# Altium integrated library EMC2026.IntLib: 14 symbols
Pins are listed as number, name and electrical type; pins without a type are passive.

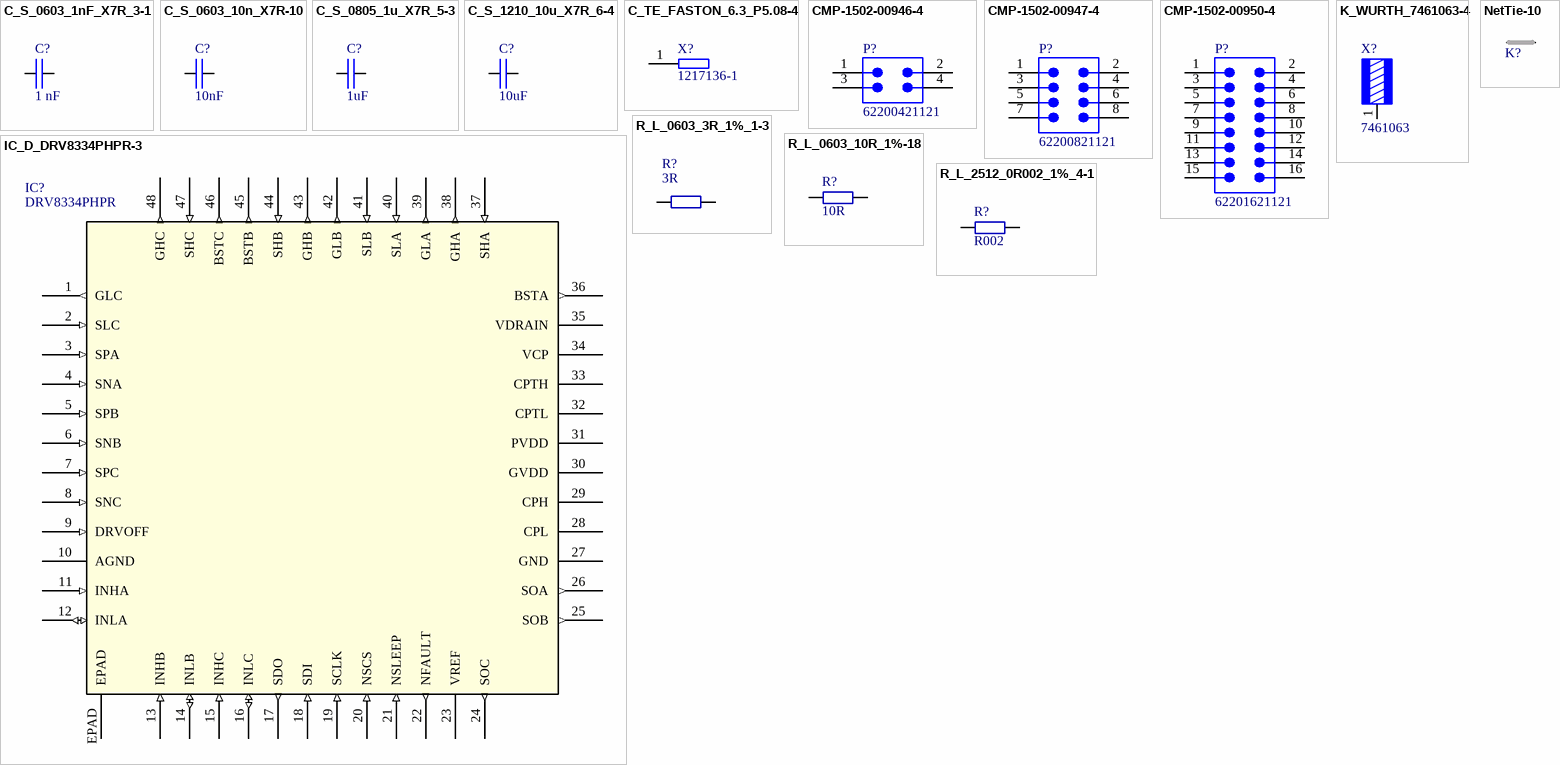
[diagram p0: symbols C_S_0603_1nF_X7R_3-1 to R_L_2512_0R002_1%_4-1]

## C_S_0603_1nF_X7R_3-1
designator C?, comment HRVal: 1 nF  (hidden comment: C_S_0603_1nF_X7R_3)
Single capacitor 1nF 5% AEC; Manufacturer code: VJ0603Y102JXAAC; Manufacturer: VISHAY; Tolerance: 5; SAP Name: KONDENZATOR VJ0603Y102JXAAC VIS; Value [F]: 1e-9; Voltage: 50; BS: BS1556; Class: 15562
footprint FPR_0603_C_R0 (SMD Reflow)
pins: 1, 2

## C_S_0603_10n_X7R-10
designator C?, comment HRVal: 10nF  (hidden comment: C_S_0603_10n_X7R)
Single capacitor 10 nF; Manufacturer code: 06035C103K4Z4A; Manufacturer: AVX; SAP Name: KONDENZATOR 06035C103K4Z4A AVX; Voltage: 50; BS: BS1556; Class: 15562; Tolerance: 10; Value [F]: 10e-9; SAP Ident: 628870
footprint FPR_0603_C_R0 (SMD Reflow)
pins: 1, 2

## C_S_0805_1u_X7R_5-3
designator C?, comment HRVal: 1uF  (hidden comment: C_S_0805_1u_X7R_5)
Single capacitor 1uF 10% soft-term AEC200; Manufacturer: Murata; Manufacturer code: GCJ21BR71H105KA01L; SAP Name: KONDENZATOR GCJ21BR71H105KA01L MUR; BS: BS1556; Tolerance: 10; Value [F]: 1e-6; Voltage: 50; SAP Ident: 927197; Class: 15562
footprint FPR_0805_C_R0_1 (SMD Reflow)
pins: 1, 2

## C_S_1210_10u_X7R_6-4
designator C?, comment HRVal: 10uF  (hidden comment: C_S_1210_10u_X7R_6)
Single capacitor 10uF; Manufacturer: AVX; Manufacturer code: 12105C106K4Z4A; BS: BS1556; SAP Name: KONDENZATOR 12105C106K4Z4A AVX; Tolerance: 10; Value [F]: 10e-6; Voltage: 50; SAP Ident: 919177; Class: 15562; Shelf life: 12 months
footprint FPR_1210_C_R0_10u (SMD Reflow)
pins: 1, 2

## C_TE_FASTON_6.3_P5.08-4
designator X?, comment Manufacturer code: 1217136-1  (hidden comment: C_TE_FASTON_6.3_P5.08)
FASTON 6.3 P5.08 Pokončni; Manufacturer: TE CONNECTIVITY; Voltage: /; SAP Ident: 1163972; SAP Name: KONEKTOR 1217136-1 TEC; BS: BS1552; AEC: No; Class: 15526
footprint FPR_TAB_6.3_P5.08_Pokončni (FASTON 6.3 P5.08 Pokončni)
pins: 1

## CMP-1502-00946-4
designator P?, comment 62200421121
THT Vertical Pin Header WR-PHD, Pitch 1.27 mm, Dual Row, 4 pins; Row Spacing: 1.27mm; Gender: Male; Number of Positions: 4; Contact Resistance: 20mΩ; Current Rating: 1A; System: Connector; Connector Type: Male Pin
footprint 62200421121 (THT Vertical Pin Header WR-PHD, Pitch 1.27 mm, Dual Row, 4 pins)
pins: 1, 2, 3, 4

## CMP-1502-00947-4
designator P?, comment 62200821121
THT Vertical Pin Header WR-PHD, Pitch 1.27 mm, Dual Row, 8 pins; System: Connector; Row Spacing: 1.27mm; Connector Type: Male Pin; Contact Resistance: 20mΩ; Number of Contacts: 8; Current Rating: 1A; Gender: Male
footprint 62200821121 (THT Vertical Pin Header WR-PHD, Pitch 1.27 mm, Dual Row, 8 pins)
pins: 1, 2, 3, 4, 5, 6, 7, 8

## CMP-1502-00950-4
designator P?, comment 62201621121
THT Vertical Pin Header WR-PHD, Pitch 1.27 mm, Dual Row, 16 pins; Number of Positions: 16; Pitch: 1.27mm; Connector Type: Male Pin; Gender: Male; Current Rating: 1A; Contact Resistance: 20mΩ; System: Connector
footprint 62201621121 (THT Vertical Pin Header WR-PHD, Pitch 1.27 mm, Dual Row, 16 pins)
pins: 1, 2, 3, 4, 5, 6, 7, 8, 9, 10, 11, 12, 13, 14, 15, 16

## IC_D_DRV8334PHPR-3
designator IC?, comment Manufacturer code: DRV8334PHPR  (hidden comment: IC_D_DRV8334PHPR)
Three phase MOSFET driver; Manufacturer: TI; AEC: No; BS: BS1557; Class: 15571; Output Current: 1000 / 2000 mA; Output Voltage: 60; SAP Ident: 1125019; SAP Name: GONILNIK DRV8334PHPR TI
footprint FPR_HTQFP_48P (SMD HTQFP 48P)
pins: 1 GLC (out), 2 SLC (in), 3 SPA (in), 4 SNA (in), 5 SPB (in), 6 SNB (in), 7 SPC (in), 8 SNC (in), 9 DRVOFF (in), 10 AGND (power), 11 INHA (in), 12 INLA (io), 13 INHB (in), 14 INLB (io), 15 INHC (in), 16 INLC (io), 17 SDO (out), 18 SDI (in), 19 SCLK (in), 20 NSCS (in), 21 NSLEEP (in), 22 NFAULT (out), 23 VREF (power), 24 SOC (out), 25 SOB (out), 26 SOA (out), 27 GND (power), 28 CPL (power), 29 CPH (power), 30 GVDD (power), 31 PVDD (power), 32 CPTL (power), 33 CPTH (power), 34 VCP (power), 35 VDRAIN (power), 36 BSTA (out), 37 SHA (in), 38 GHA (out), 39 GLA (out), 40 SLA (in), 41 SLB (in), 42 GLB (out), 43 GHB (out), 44 SHB (in), 45 BSTB (out), 46 BSTC (out), 47 SHC (in), 48 GHC (out), EPAD

## K_WURTH_7461063-4
designator X?, comment Manufacturer code: 7461063  (hidden comment: K_WURTH_7461063)
Connector POWER Wurth 7461063; Manufacturer: WURTH ELEKTRONIK; UL: /; MaxCurrent: 160; AEC: No; Class: 15526; ReleaseDateNum: 45705.4409943981; Voltage: 300; BS: BS1552; SAP Name: KONEKTOR 7461063 WUE; SAP Ident: 1144983
footprint FPR_K_1P_WURTH (WURTH 1P terminal connector)
pins: 1

## NetTie-10
designator K?, comment NetTie  (value not drawn)  (net tie, no BOM)
Net tie
footprint FPR_NETTIE_0_3 (Net tie, 0.3 mm)
pins: 1, 2

## R_L_0603_3R_1%_1-3
designator R?, comment HRVal: 3R  (hidden comment: R_L_0603_3R_1%_1)
Upor 3R 0603 1% 100mW; Manufacturer code: CRCW06033R00FKEA; Manufacturer: VISHAY; SAP Name: UPOR CRCW06033R00FKEA VIS; Tolerance: 1; Power: 100e-3; ReleaseDateNum: 45455.4806185648; BS: BS1556; Class: 15561; Value [Ohm]: 3; SAP Ident: 1125027
footprint FPR_0603_R_R0_1 (SMD Reflow)
pins: 1, 2

## R_L_0603_10R_1%-18
designator R?, comment HRVal: 10R  (hidden comment: R_L_0603_10R_1%)
Upor 10R 0603 1% 100mW; Manufacturer: ASJ; Manufacturer code: CR16-10R0-FY; Class: 15561; BS: BS1556; Shelf life: 12 months; SAP Name: UPOR CR16-10R0-FY ASJ; SAP Ident: 220173; Tolerance: 1; Power: 100e-3; Value [Ohm]: 10
footprint FPR_0603_R_R0 (SMD Reflow)
simulation model GenericR
footprint FPR_0603_R_R0_1 (SMD Reflow)
pins: 1, 2

## R_L_2512_0R002_1%_4-1
designator R?, comment HRVal: R002  (hidden comment: R_L_2512_0R002_1%_4)
Upor 0R002 2512 1% AEC; Manufacturer code: WSLF25122L000FEA; Manufacturer: VISHAY; SAP Name: UPOR WSLF25122L000FEA VIS; Cat1: 2512; Value [Ohm]: 2e-3; Power: 5; Class: 15561; Tolerance: 1; Shelf life: 24mo; SAP Ident: ******; BS: BS1556
footprint FPR_2512_R_R1 (SMD resistor 2512 Reflow)
pins: 1, 2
